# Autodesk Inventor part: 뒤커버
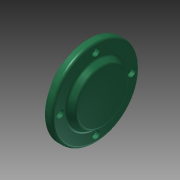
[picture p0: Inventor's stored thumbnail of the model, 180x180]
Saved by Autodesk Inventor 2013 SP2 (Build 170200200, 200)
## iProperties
Created: 2015-11
Part Number: 뒤커버
Material: 알루미늄 6061
Document SubType Name: Modeling
Designer: mduedu
Density: 2.71 g/cm^3
Author: mduedu
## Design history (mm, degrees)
sketch "스케치1"
  geometry: C1 r 47.5 at (0, 0); 1 further point
  constraints: 1 centre point, 1 coincident
  dimensions: "d42" = 95 diameter of C1
extrude "돌출1" new body sketch "스케치1" distance "d3" = 8; taper "d4" = 0 deg
sketch "스케치2"
  geometry: C1 r 32.5 at (0, 0); 1 further point
  constraints: 1 centre point, 1 coincident
  dimensions: "d5" = 65 diameter of C1
extrude "돌출2" join sketch "스케치2" distance "d6" = 7; taper "d7" = -30 deg
sketch "스케치5" dims "d44" = 78
  geometry: 3 further points
  constraints: 2 vertical alignment, 1 coincident, 2 other
hole "구멍3" sketch "스케치5" at (0, 39) diameter "d45" = 4.5; stored, may be unused: countersink angle "d49" = 90 deg, drill point angle "d51" = 118 deg; dims "d46" = 6, "d47" = 8, "d48" = 4.4, "d50" = 8
sketch "스케치4"
  geometry: C1 r 32.5 at (0, 0); 1 further point
  constraints: 1 centre point, 1 coincident
  dimensions: "d21" = 65 diameter of C1
extrude "돌출3" join sketch "스케치4" distance "d23" = 12; taper "d24" = 0 deg
hole "구멍2" diameter "d27" = 34; stored, may be unused: countersink angle "d31" = 90 deg, drill point angle "d33" = 0 deg; dims "d28" = 6, "d29" = 40, "d30" = 12, "d32" = 15, "d62" = 10, "d63" = 10
fillet "모깎기3" dims "d36" = 3
fillet "모깎기4" dims "d37" = 3
fillet "모깎기5" dims "d38" = 0.3
chamfer "모따기1" distance "d39" = 1; stored, may be unused: second distance "d40" = 2, angle "d41" = 45 deg
node "솔리드1"
pattern_circular "원형 패턴2" dims angle "d53" = 360 deg
